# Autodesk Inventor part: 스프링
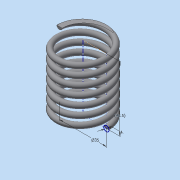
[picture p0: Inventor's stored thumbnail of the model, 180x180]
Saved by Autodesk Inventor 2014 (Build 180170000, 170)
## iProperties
Created: 2014-12
Part Number: 스프링
Material: 일반
Document SubType Name: Modeling
Designer: user
Density: 1 g/cm^3
Appearance: 기본값
Author: user
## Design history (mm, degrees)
sketch "스케치1"
  geometry: L1 (0, 0)-(17.5, 0); L2 (17.5, 0)-(17.5, 48.5); L3 (17.5, 48.5)-(0, 48.5); L4 (0, 48.5)-(0, 0); C1 r 2 at (17.5, 0)
  constraints: 8 end point, 2 parallel, 1 centre point, 1 coincident, 1 horizontal, 1 perpendicular
  dimensions: "d0" = 35 diameter of L2 L4; "d1" = 48.5 distance between parallel lines of L1 L3 (derived); "d2" = 4 diameter of C1
feature "코일1" sketch "스케치1" pitch "d3" = 10; turns "d5" = 7.5; dims "d4" = 48.5 (= d1), "d6" = 0, angle "d7" = 90 deg, angle "d8" = 90 deg, "d9" = 0, "d10" = 0
sketch "스케치3"
  geometry: L1 (-19.5, 0)-(-15.5, 0) reference; 1 further point
  constraints: 1 horizontal alignment
extrude "돌출1" cut sketch "스케치3" stored distance "d11" = 10; taper "d12" = 0 deg
node "작업 평면1"
sketch "스케치4"
  geometry: L1 (-4, 0)-(0, 0) reference; 1 further point
  constraints: 1 horizontal alignment
extrude "돌출2" cut sketch "스케치4" stored distance "d13" = 10; taper "d14" = 0 deg
node "솔리드1"
node "절단 모서리 투영2"
node "절단 모서리 투영3"
